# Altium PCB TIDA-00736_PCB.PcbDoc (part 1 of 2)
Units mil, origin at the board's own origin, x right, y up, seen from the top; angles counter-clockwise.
Board outline 3346.46 x 1968.5 mil, 2 copper layers (Top Layer, Bottom Layer), stack 62 mil thick; 81 components, 63 nets, 308 pads, 545 vias.
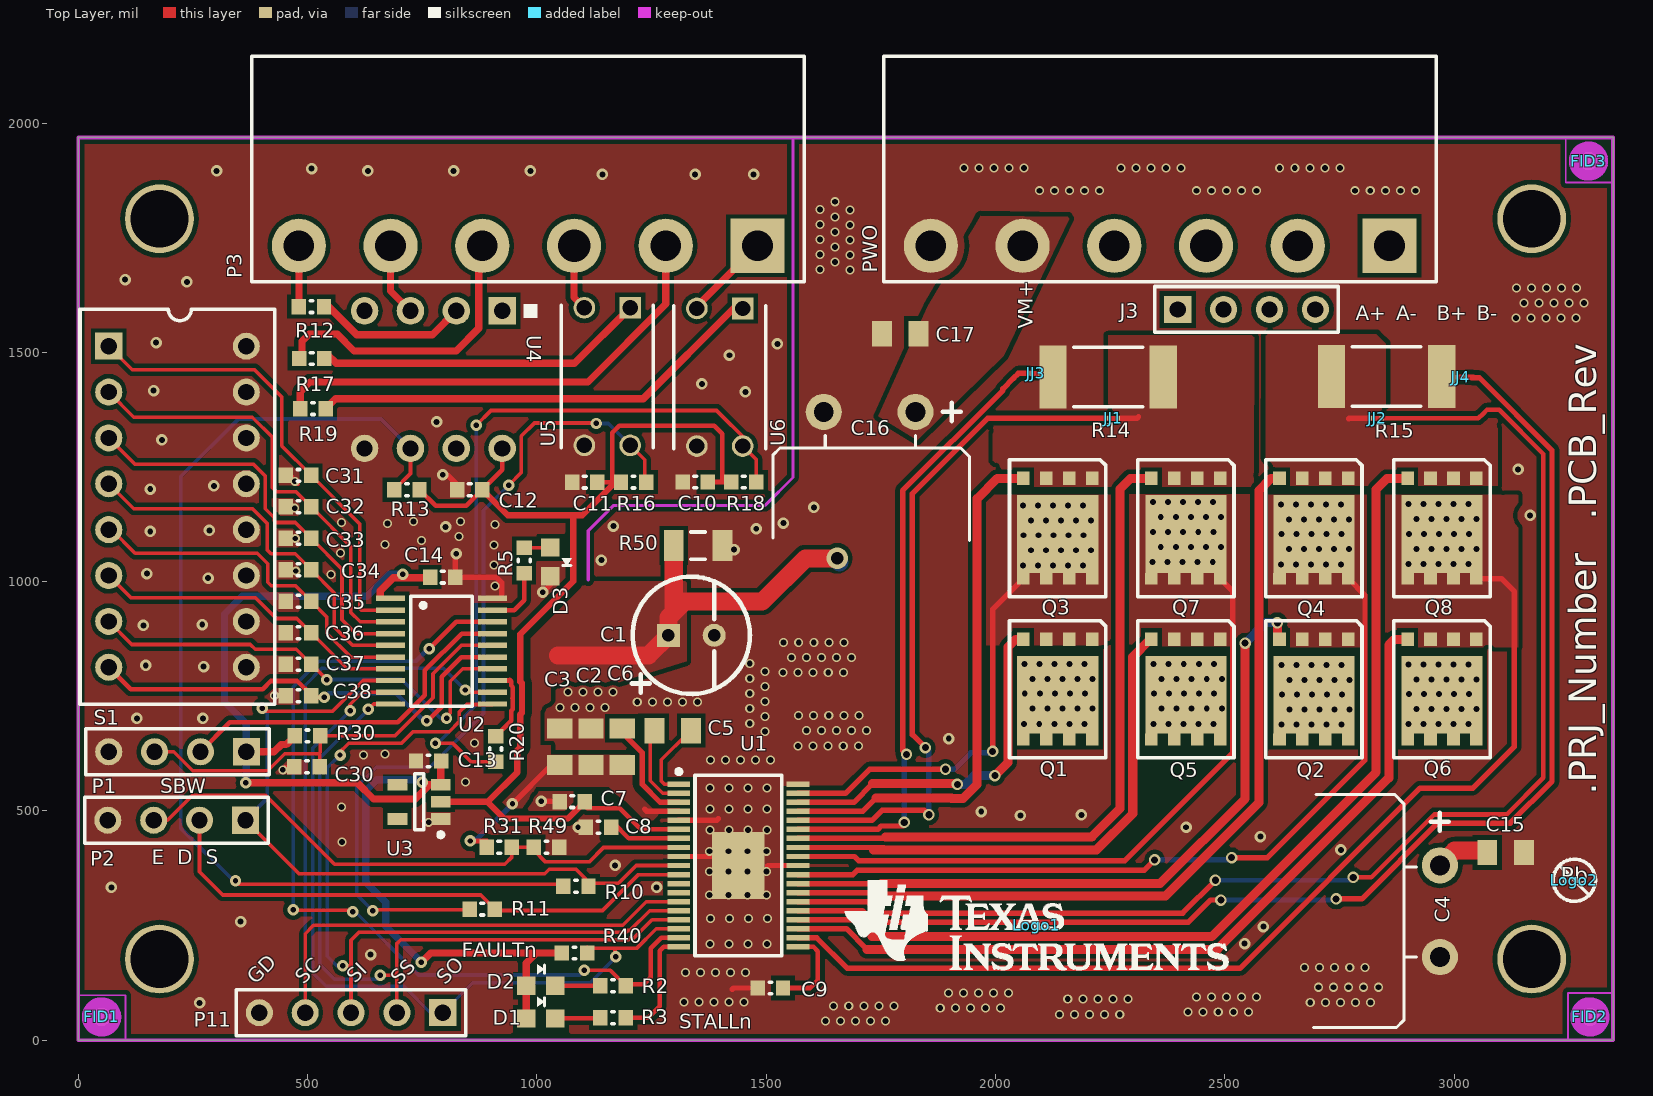
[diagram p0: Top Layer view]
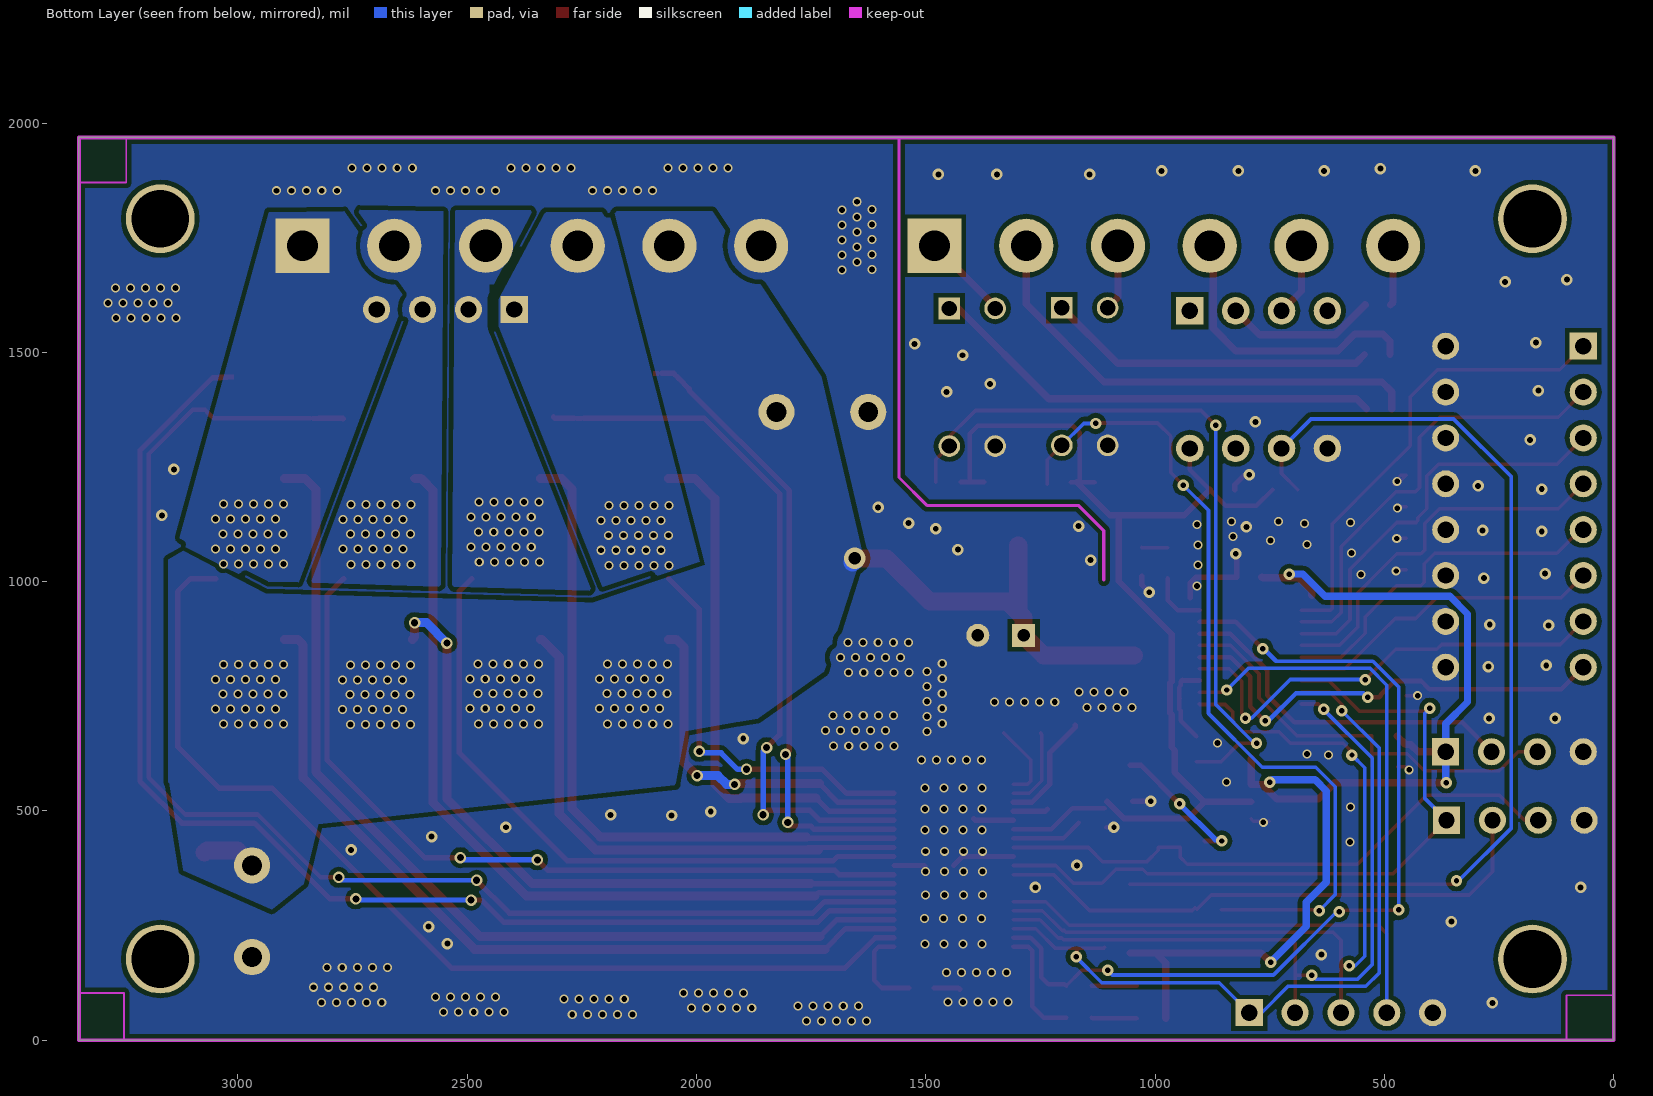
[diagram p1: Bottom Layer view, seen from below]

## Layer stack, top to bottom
Top Solder: solder mask 0.4, Solder Resist, Dk 3.5
Top Layer: signal copper 1.4
Dielectric1: core 59.2, FR-4, Dk 4.8
Bottom Layer: signal copper 1.4
Bottom Solder: solder mask 0.4, Solder Resist, Dk 3.5

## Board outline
0,0 3346.46,0 3346.46,1968.5 0,1968.5

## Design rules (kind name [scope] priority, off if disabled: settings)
AcuteAngle [All] p1: minimum=4.50000000000000E+0001 checktracksonly=FALSE
AssemblyTestPointUsage [All] p1: valid=2
Clearance Clearance_Keepouts [((IsTrack Or IsArc) And Not InPoly) And IsFree and IsKeepOut vs ((IsTrack Or IsArc) And Not InPoly) And IsFree and IsKeepOut] p1: gap=0
Clearance Clearance_BoardEdge_MountingHoles [OnCopper and InComponentClass('Mounting Holes') vs IsKeepOut] p2: gap=8
Clearance Clearance_BoardEdge_Poly [OnCopper and InPoly vs IsKeepOut] p3: gap=10
Clearance Clearance_BoardEdge [OnCopper and Not InComponentClass('Logo') and not InComponentClass('FiducialMark') and not InRegion(1000,500,4000,800) and Not IsKeepout vs IsKeepOut] p4: gap=10
Clearance Clearance_Poly [InPolygon] p5: gap=10
Clearance [All] p6: gap=7.87
ComponentClearance ComponentClearance_MountingHoles_FiducialMarks [InComponentClass('Mounting Holes') vs InComponentClass('FiducialMark')] p1: gap=50 collisioncheckmode=3 verticalgap=10 showdistances=FALSE
ComponentClearance ComponentClearance_Shunt [InComponentClass('Header') vs InComponentClass('Shunt')] p2: gap=0 collisioncheckmode=3 verticalgap=0 showdistances=FALSE
ComponentClearance ComponentClearance_Logo [InComponentClass('Logo')] p3: gap=50 collisioncheckmode=3 verticalgap=10 showdistances=FALSE
ComponentClearance ComponentClearance_ScrewToNut [(HasFootprint('NY PMS 440 0025 PH')) vs (HasFootprint('Keystone_1902C'))] p4: gap=5 collisioncheckmode=3 verticalgap=10 showdistances=FALSE
ComponentClearance ComponentClearance_MountingHoles [InComponentClass('Mounting Holes')] p5: gap=250 collisioncheckmode=3 verticalgap=100000 showdistances=FALSE
ComponentClearance ComponentClearance_SmallPassives [HasFootprint('0201*') or HasFootprint('0402*') or HasFootprint('0508') or HasFootprint('0603*') or HasFootprint('0612') or HasFootprint('0805*') or HasFootprint('0815*') or HasFootprint('0830*') or HasFootprint('1206*') or HasFootprint('1210*') or HasFootprint('1808*') or HasFootprint('1812*') or HasFootprint('1825*') or HasFootprint('2010*') or HasFootprint('2220*') or HasFootprint('2225*') or HasFootprint('2512*') or HasFootprint('2728*') or HasFootprint('3518*') vs HasFootprint('0201*') or HasFootprint('0402*') or HasFootprint('0508') or HasFootprint('0603*') or HasFootprint('0612') or HasFootprint('0805*') or HasFootprint('0815*') or HasFootprint('0830*') or HasFootprint('1206*') or HasFootprint('1210*') or HasFootprint('1808*') or HasFootprint('1812*') or HasFootprint('1825*') or HasFootprint('2010*') or HasFootprint('2220*') or HasFootprint('2225*') or HasFootprint('2512*') or HasFootprint('2728*') or HasFootprint('3518*')] p6: gap=10 collisioncheckmode=3 verticalgap=10 showdistances=FALSE
ComponentClearance ComponentClearance_THtoSMT [IsThruComponent vs IsSMTComponent] p7: gap=10 collisioncheckmode=3 verticalgap=1 showdistances=FALSE
ComponentClearance ComponentClearance_THtoTH [IsThruComponent vs IsThruComponent] p8: gap=1 collisioncheckmode=3 verticalgap=0 showdistances=FALSE
ComponentClearance [All] p9: gap=8 collisioncheckmode=3 verticalgap=10 showdistances=FALSE
DiffPairsRouting [All] p1: maxlimit=100 minlimit=10 mostfreqgap=10 toplayer_minwidth=15 toplayer_maxwidth=15 toplayer_prefwidth=15 bottomlayer_minwidth=15 bottomlayer_maxwidth=15 bottomlayer_prefwidth=15 maxuncoupledlength=1000
FabricationTestPointUsage TestPointUsage [All] p1: valid=2 allowmultiple=FALSE
FabricationTestpoint Testpoint [All] p1: side=3 testpointundercomponent=TRUE minsize=40 maxsize=100 preferedsize=60 minholesize=0 maxholesize=40 preferedholesize=32 testpointgrid=1 allowsidetop=TRUE allowsidebottom=TRUE usegrid=TRUE gridtolerance=0.01
FanoutControl Fanout_LCC [IsLCC] p1: bgadir=Out bgaviamode=Centered fanoutstyle=Auto fanoutdirection=Alternating viagrid=1 // Fanout_LCC (Default Rule)
FanoutControl Fanout_BGA [IsBGA] p2: bgadir=Out bgaviamode=Centered fanoutstyle=Auto fanoutdirection=Alternating viagrid=1 // Fanout_BGA (Default Rule)
FanoutControl Fanout_Default [All] p4: bgadir=Out bgaviamode=Centered fanoutstyle=Auto fanoutdirection=Alternating viagrid=1 // Fanout_Default (Default Rule)
FanoutControl Fanout_Small [(CompPinCount < 5)] p5: bgadir=Out bgaviamode=Centered fanoutstyle=Auto fanoutdirection=OutThenIn viagrid=1 // Fanout_Small (Default Rule)
HoleSize [All] p1: absolutevalues=TRUE maxlimit=251 minlimit=8 maxpercent=80.000 minpercent=20.000
MinimumAnnularRing MinimumAnnularRing_ThermalPadVias [IsVia and InAnyComponent] p1: minimumring=5.91
MinimumAnnularRing [All] p2: minimumring=9
MinimumSolderMaskSliver MinimumSolderMaskSliver_Logo [InComponentClass('Logo') vs InComponentClass('Logo')] p1: minsoldermaskwidth=0.7
MinimumSolderMaskSliver [All] p2: minsoldermaskwidth=3.94
PlaneClearance [All] p1: clearance=15
PlaneConnect [All] p1: planeconnectstyle=Direct reliefexpansion=10 reliefentries=4 reliefconductorwidth=10 reliefairgap=10
PolygonConnect [All] p1: connectstyle=Direct reliefconductorwidth=10 reliefentries=4 polygonreliefangle="90 Angle" airgapwidth=10
RoutingVias ThermalPadVias [IsVia and InAnyComponent] p1: holewidth=7.87 width=19.68 viastyle="Through Hole" minholewidth=7.87 minwidth=19.68 maxholewidth=12.99 maxwidth=23.62
RoutingVias [All] p2: holewidth=16 width=34 viastyle="Through Hole" minholewidth=7.87 minwidth=25 maxholewidth=40 maxwidth=65
SilkToBoardRegionClearance [Not ((IsComment or IsDesignator) And (Hide <> 'False')) and not InRegion(1000,500,4000,800)] p1:
SilkToSilkClearance SilkToSilkClearance_Pb-FreeLogo [(HasFootprint('Pb-Free_Overlay_Medium') OR HasFootprint('Pb-Free_Overlay_Small')) vs (HasFootprint('Pb-Free_Overlay_Medium') OR HasFootprint('Pb-Free_Overlay_Small'))] p1: silktosilkclearance=0
SilkToSilkClearance [All] p2: silktosilkclearance=4
SilkToSolderMaskClearance SilkToComonentPadClearance [IsPad and InAnycomponent] p1: minsilkscreentomaskgap=5 clearancetoexposedcopper=TRUE
SilkToSolderMaskClearance "Silk to Solder Mask Opening" [All] p2: minsilkscreentomaskgap=4 clearancetoexposedcopper=FALSE
SolderMaskExpansion [All] p1: expansion=1.97
UnpouredPolygon [All] p1: allowunpoured=FALSE
Width [All] p1: maxlimit=100 minlimit=6 preferedwidth=10 checkconnectedcopper=TRUE
13 further rules are at their usual default settings.

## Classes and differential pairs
component class TIDA-00736_SCH: C1 C2 C3 C4 C5 C6 C7 C8 C9 C10 C11 C12 C13 C14 C15 C16 C17 C30 C31 C32 C33 C34 C35 C36 C37 C38 D1 D2 D3 J3 JJ1 JJ2 JJ3 JJ4 P1 P2 P3 P11 PWO Q1 Q2 Q3 Q4 Q5 Q6 Q7 Q8 R2 R3 R5 R10 R11 R12 R13 R14 R15 R16 R17 R18 R19 R20 R30 R31 R40 R49 R50 S1 U1 U2 U3 U4 U5 U6
component class Header: J3 P1 P2 P11
component class AssemblyNote: ZZ2 ZZ3 ZZ4
component class FiducialMark: FID1 FID2 FID3
component class TIDA-00736_Hardware: FID1 FID2 FID3 Logo1 Logo2 ZZ2 ZZ3 ZZ4
component class Logo: Logo1

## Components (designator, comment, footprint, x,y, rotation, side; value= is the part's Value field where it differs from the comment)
C1 "UBT2A220MPD1TD" "RB .1/.250 - SML" 1386.61,883.07 r0 top
C2 "C2012X7R2A104K" C0805M 1118,640 r90 top
C3 "08051C103JAT2A" C0805M 1050,640 r90 top
C4 "EKYB630ELL331MJ25S" CAP13-5 2968.9,181.5 r270 top locked
C5 "C2012X7R2A104K" C0805M 1296.46,675.2 r180 top
C6 "08055C105KAT2A" C0805M 1186,640 r270 top
C7 "C0603X104K4RACTU" 0603l 1077.17,520.47 r180 top
C8 "C0603C105K4PACTU" 0603l 1134.25,464.57 r180 top
C9 "885012206034" 0603l 1509.06,114.17 r180 top
C10 "CGA3E2X8R1E104K080AA" 0603l 1345.28,1217.32 r0 top
C11 "CGA3E2X8R1E104K080AA" 0603l 1104.33,1216.93 r0 top
C12 "CGA3E2X8R1E104K080AA" 0603l 853.54,1200.39 r0 top
C13 "C0603C105K4PACTU" 0603l 764,609 r0 top
C14 "C0603C105K4PACTU" 0603l 794.88,1009.84 r180 top
C15 "C2012X7R2A104K" C0805M 3112.21,409.45 r180 top
C16 "860040875005" CAP10-5 1825.59,1370.08 r0 top locked
C17 "C2012X7R2A104K" C0805m 1792.35,1540.61 r0 top
C30 "885012206034" 0603l 498.82,596.46 r0 top
C31 "CGA3E2X8R1E104K080AA" 0603l 480.32,1231.89 r0 top
C32 "CGA3E2X8R1E104K080AA" 0603l 480.32,1163.22 r0 top
C33 "CGA3E2X8R1E104K080AA" 0603l 480.32,1094.54 r0 top
C34 "CGA3E2X8R1E104K080AA" 0603l 480.32,1025.87 r0 top
C35 "CGA3E2X8R1E104K080AA" 0603l 480.32,957.2 r0 top
C36 "CGA3E2X8R1E104K080AA" 0603l 480.32,888.53 r0 top
C37 "CGA3E2X8R1E104K080AA" 0603l 480.32,819.85 r0 top
C38 "CGA3E2X8R1E104K080AA" 0603l 480.32,751.18 r0 top
D1 "LTST-C191KRKT" LED603RED 1007.87,47.64 r180 top
D2 "LTST-C191KRKT" LED603RED 1007.87,118.9 r180 top
D3 "LTST-C191TGKT" LED603RED 1029.13,1043.7 r90 top
FID1 "Fiducial" Fiducial10-20 51,51 r0 top
FID2 "Fiducial" Fiducial10-20 3296,51 r0 top
FID3 "Fiducial" Fiducial10-20 3293,1917 r0 top
J3 "800-10-004-10-001000" HDR1X4 2397.35,1593.61 r0 top
JJ1 "Net-Tie" NETCC 2256.3,1355.91 r0 top net-tie
JJ2 "Net-Tie" NETCC 2832.28,1355.91 r180 top net-tie
JJ3 "Net-Tie" NETCC 2088,1454 r0 top net-tie
JJ4 "Net-Tie" netcc 3014.57,1446.06 r180 top net-tie
Logo1 "Texas Instruments" TI_Stacked_Overlay_Small 2090,251 r0 top
Logo2 "Pb-Free Symbol" Pb-Free_Overlay_Small 3262,349 r0 top
P1 "800-10-004-10-001000" HDR1X4 366.54,629.13 r180 top
P2 "800-10-004-10-001000" HDR1X4 364.57,479.92 r180 top
P3 "Header 6" cn508-6 1181.1,1732.28 r180 top locked
P11 "800-10-005-10-001000" HDR1X5 794.88,60.24 r180 top
PWO "Header 6" cn508-6 2559.06,1732.28 r180 top locked
Q1 "CSD18531Q5A" PQFN8 2210.63,874.41 r90 top
Q2 "CSD18531Q5A" PQFN8 2769.16,874.41 r90 top
Q3 "CSD18531Q5A" PQFN8 2210.63,1225.08 r90 top locked
Q4 "CSD18531Q5A" PQFN8 2769.16,1225.08 r90 top
Q5 "CSD18531Q5A" PQFN8 2489.9,874.41 r90 top
Q6 "CSD18531Q5A" PQFN8 3048.43,874.41 r90 top
Q7 "CSD18531Q5A" PQFN8 2489.9,1225.08 r90 top
Q8 "CSD18531Q5A" PQFN8 3048.43,1225.08 r90 top
R2 "RC0603JR-0710KL" 0603l 1166.14,119.06 r180 top
R3 "RC0603JR-0710KL" 0603l 1166.14,49.21 r180 top
R5 "RC0603JR-0710KL" 0603l 972.44,1046.06 r270 top
R10 "CRCW0603470RJNEA" 0603l 1085,336 r180 top
R11 "CRCW0603470RJNEA" 0603l 881,286 r180 top
R12 "CRCW0603220RJNEA" 0603l 508.35,1599.61 r180 top
R13 "CRCW06033K30JNEA" 0603l 716.54,1200.39 r180 top
R14 "CRA2512-FZ-R040ELF" 2512M 2245.67,1446.46 r0 top
R15 "CRA2512-FZ-R040ELF" 2512M 2852.76,1447.24 r180 top
R16 "CR0603-JW-472GLF" 0603l 1211.02,1216.93 r0 top
R17 "CRCW0603220RJNEA" 0603l 509.35,1486.61 r180 top
R18 "CR0603-JW-472GLF" 0603l 1451.18,1217.32 r0 top
R19 "CRCW0603220RJNEA" 0603l 511.81,1377.17 r180 top
R20 "CRCW0603470RJNEA" 0603l 910,635 r270 top
R30 "CRCW060347K0JNEA" 0603l 500,663.78 r0 top
R31 "CRCW0603100KJNEA" 0603l 918,421 r0 top
R40 "CRCW060347K0JNEA" 0603l 1082.28,190.55 r0 top
R49 "RC0603JR-0710KL" 0603l 1021,421 r0 top
R50 "CRCW120610K0JNEA" C1206 1351.58,1078.74 r0 top
S1 "76SB08ST" DIP-16-KEY 66.54,1513.39 r270 top
U1 "DRV8711" "DCP38 SMT" 1309.45,558.27 r270 top
U2 "MSP430G2202IPW20" DGV0020A_L 792.13,848.43 r0 top
U3 "TLV70433DBVR" MF05A_N 743.31,520.08 r180 top
U4 "6N137S(TA)" DIP8 774.41,1440.55 r180 top
U5 "PC817X4NSZ0F" DIP762W60P254L460H350Q4B 1153.54,1447.24 r270 top
U6 "PC817X4NSZ0F" DIP762W60P254L460H350Q4B 1398.82,1445.67 r270 top
ZZ2 "These assemblies are ESD sensitive, ESD precautions shall be observed." AssemblyNote -96.65,3428.72 r0 top
ZZ3 "These assemblies must be clean and free from flux and all contaminants. Use of no clean flux is not acceptable." AssemblyNote -96.65,3340.16 r0 top
ZZ4 "These assemblies must comply with workmanship standards IPC-A-610 Class 2, unless otherwise specified." AssemblyNote -96.65,3251.61 r0 top

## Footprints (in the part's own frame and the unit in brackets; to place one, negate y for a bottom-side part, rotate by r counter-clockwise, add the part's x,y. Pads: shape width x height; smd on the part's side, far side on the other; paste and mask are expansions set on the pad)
0603l [mm] "0603 from SM-752 data"
  rect 0.8x0.85 smd: 1(-0.7,0) 2(0.7,0)
  silkscreen extent -0.07,-0.33 0.07,0.33, body extent -0.87,-0.47 0.87,0.47, height 0.85
2512M [mm] "Chip Resistor, Body 6.3x3.2mm, IPC Low Density"
  rect 1.5x3.5 smd: 1(-3.05,0) 2(3.05,0)
  silkscreen extent -1.9,-1.65 1.9,1.65, body extent -3.22,-1.67 3.22,1.67, height 0.71
AssemblyNote [mil] "Assembly Note"
C0805M [mm]
  rect 1.1x1.4 smd: 1(-1.016,0) 2(1.016,0)
  body extent -1.1,-0.72 1.1,0.72, height 1.4
C0805m [mm]
  rect 1.1x1.4 smd: 1(-1.016,0) 2(1.016,0)
  body extent -1.1,-0.72 1.1,0.72, height 1.4
C1206 [mm] "Chip Capacitor, Body 3.2x1.6mm, IPC High Density"
  rect 1.1x1.7 smd: 1(-1.35,0) 2(1.35,0)
  silkscreen extent -0.4,-0.75 0.4,0.75, body extent -1.7,-0.9 1.7,0.9, height 1.3
CAP10-5 [mm] "Small Form Factor"
  round 2 hole 1.1: 1(0,0) 2(-5.08,0)
  silkscreen extent -7.9,-7.11 3,0.5
CAP13-5 [mm] "Small Form Factor"
  round 2 hole 1.1: 1(-5.08,0) 2(0,0)
  silkscreen extent -9,-6.98 3.9,0.5
cn508-6 [mm] "Connector; Header; 4 Position"
  rect 3x3 hole 1.7: 1(-7.62,0)
  round 3 hole 1.7: 2(-2.54,0) 4(7.62,0) 5(12.7,0) 6(17.78,0)
  round 3 hole 1.8: 3(2.54,0)
  silkscreen extent -10.2,-10.5 20.4,2
"DCP38 SMT" [mm] "DCP 38 Pin  Solder"
  rect 3.7x2.9 smd: 0(4.5,3.3)
  rect 0.3x1.25 smd: 1(0,0) 2(0.5,0) 3(1,0) 4(1.5,0) 5(2,0) 6(2.5,0) 7(3,0) 8(3.5,0) 9(4,0) 10(4.5,0) 11(5,0) 12(5.5,0) 13(6,0) 14(6.5,0) 15(7,0) 16(7.5,0) 17(8,0) 18(8.5,0) 19(9,0) 20(9,6.6) 21(8.5,6.6) 22(8,6.6) 23(7.5,6.6) 24(7,6.6) 25(6.5,6.6) 26(6,6.6) 27(5.5,6.6) 28(5,6.6) 29(4.5,6.6) 30(4,6.6) 31(3.5,6.6) 32(3,6.6) 33(2.5,6.6) 34(2,6.6) 35(1.5,6.6) 36(1,6.6) 37(0.5,6.6) 38(0,6.6)
  silkscreen extent -0.82,-0.12 9.5,5.7
DGV0020A_L [mm] "TSSOP, 20-Leads, Body 5x4.4mm, Pitch 0.4mm, IPC High Density"
  rect 1.6x0.3 smd: 1(-2.825,2.925) 2(-2.825,2.275) 3(-2.825,1.625) 4(-2.825,0.975) 5(-2.825,0.325) 6(-2.825,-0.325) 7(-2.825,-0.975) 8(-2.825,-1.625) 9(-2.825,-2.275) 10(-2.825,-2.925) 11(2.825,-2.925) 12(2.825,-2.275) 13(2.825,-1.625) 14(2.825,-0.975) 15(2.825,-0.325) 16(2.825,0.325) 17(2.825,0.975) 18(2.825,1.625) 19(2.825,2.275) 20(2.825,2.925)
  silkscreen extent -1.7,-3.05 1.7,3.05
DIP8 [mil]
  rect 60x60 hole 35.43: 1(-150,-150)
  round 60 hole 35.43: 2(-50,-150) 3(50,-150) 4(150,-150) 5(150,150) 6(50,150) 7(-50,150) 8(-150,150)
  silkscreen extent -227,-165 -197,-135
DIP762W60P254L460H350Q4B [mm] "LITE-ON"
  rect 1.2x1.2 hole 0.85: 1(-3.81,1.27)
  round 1.2 hole 0.85: 2(-3.81,-1.27) 3(3.81,-1.27) 4(3.81,1.27)
  silkscreen extent -3.96,-2.55 3.96,2.55, body extent -3.96,-2.55 3.96,2.55, height 4.5
DIP-16-KEY [mm] "DIP; 16 Leads; Row Spacing 7.62 mm; Pitch 2.54 mm"
  rect 1.5x1.5 hole 0.9: 1(0,0)
  round 1.5 hole 0.9: 2(2.54,0) 3(5.08,0) 4(7.62,0) 5(10.16,0) 6(12.7,0) 7(15.24,0) 8(17.78,0) 9(17.78,7.62) 10(15.24,7.62) 11(12.7,7.62) 12(10.16,7.62) 13(7.62,7.62) 14(5.08,7.62) 15(2.54,7.62) 16(0,7.62)
  silkscreen extent -2.05,-1.59 19.83,9.2
Fiducial10-20 [mm]
  round 1 smd mask+0.5: 1(0,0)
  Top Layer keep-out circle w1.178: c0,0 r0.5
HDR1X4 [mm] "Connector; Header; 4 Position"
  rect 1.5x1.5 hole 0.9: 1(0,0)
  round 1.5 hole 0.9: 2(2.54,0) 3(5.08,0) 4(7.62,0)
  silkscreen extent -1.27,-1.27 8.89,1.27
HDR1X5 [mm] "Connector; Header; 5 Position"
  rect 1.5x1.5 hole 0.9: 1(0,0)
  round 1.5 hole 0.9: 2(2.54,0) 3(5.08,0) 4(7.62,0) 5(10.16,0)
  silkscreen extent -1.27,-1.27 11.43,1.27
LED603RED [mil]
  rect 40x40 smd: 1(30.8,-0.1) 2(-32.2,-0.1)
  silkscreen extent -10,-47 7,-25, body extent -26,-29 26,29, height 43
MF05A_N [mm] "SOT23, 5-Leads, Body 2.9x1.6mm, Pitch 0.95mm, Lead Span 2.8mm, IPC Medium Density"
  rect 1.1x0.65 smd: 1(-1.2,0.95) 2(-1.2,0) 3(-1.2,-0.95) 4(1.2,-0.95) 5(1.2,0.95)
  silkscreen extent -1.33,-1.55 0.25,1.95, body extent -0.9,-1.55 0.9,1.55, height 1.19
NETCC [mil] "10mil net tie, no solder mask opening, no solder paste"
  rect 10x10 smd paste-5 mask-5: 1(-10,0) 2(10,0)
  Top Layer region: -6,5 6,5 6,-5 -6,-5
netcc [mil] "10mil net tie, no solder mask opening, no solder paste"
  rect 10x10 smd paste-5 mask-5: 1(-10,0) 2(10,0)
  Top Layer region: -6,5 6,5 6,-5 -6,-5
Pb-Free_Overlay_Small [mil]
  silkscreen extent -46,-46 46,46
PQFN8 [mm]
  rect 0.75x0.7 smd: 1(0,0) 2(0,1.27) 3(0,2.54) 4(0,3.81)
  rect 0.65x0.7 smd: 5(-5.55,0) 5(-5.55,1.27) 5(-5.55,2.54) 5(-5.55,3.81)
  rect 4.3x4.5 smd: 5(-3.075,1.9)
  silkscreen extent -6.55,-0.76 1.03,4.57
"RB .1/.250 - SML" [mil] "Small Form Factor"
  rect 50x50 hole 28: 1(-100,0)
  round 50 hole 28: 2(0,0)
  silkscreen extent -180,-128 78,128
TI_Stacked_Overlay_Small [mil]
  silkscreen extent -418,-98 418,98

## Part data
C1: "CAP, AL, 22 μF, 100 V, +/- 20%, 0.8 ohm, TH"
C2 C5 C15 C17: "CAP, CERM, 0.1 μF, 100 V, +/- 10%, X7R, 0805"
C3: "CAP, CERM, 0.01 μF, 100 V, +/- 5%, X7R, 0805"
C4: "CAP, AL, 330 μF, 63 V, +/- 20%, 0.045 ohm, TH"
C6: "CAP, CERM, 1 μF, 50 V, +/- 10%, X7R, 0805"
C7: "CAP, CERM, 0.1 μF, 16 V, +/- 10%, X7R, 0603"
C8 C13 C14: "CAP, CERM, 1 μF, 16 V, +/- 10%, X5R, 0603"
C9 C30: "CAP, CERM, 1000 pF, 16 V, +/- 10%, X7R, 0603"
C10 C11 C12 C31 C32 C33 C34 C35 C36 C37 C38: "CAP, CERM, 0.1 μF, 25 V, +/- 10%, X8R, AEC-Q200 Grade 0, 0603"
C16: "CAP, AL, 100 μF, 100 V, +/- 20%, 0.2 ohm, TH"
D1 D2: "LED, Red, SMD"
D3: "LED, Green, SMD"
FID1 FID2 FID3: "Fiducial mark.  There is nothing to buy or mount."
J3 P1 P2: "Header, 100mil, 4x1, TH"
JJ1 JJ2 JJ3 JJ4: "Single point connection between nets."
Logo1: library part TI_Logo, "Texas Instrument Corporate Signature"
Logo2: library part Pb-Free
P3 PWO: "Header, 6-Pin"
P11: "Header, 100mil, 5x1, TH"
Q1 Q2 Q3 Q4 Q5 Q6 Q7 Q8: "MOSFET, N-CH, 60 V, 19 A, SON 5x6mm"
R2 R3 R5 R49: "RES, 10 k, 5%, 0.1 W, 0603"
R10 R11 R20: "RES, 470, 5%, 0.1 W, 0603"
R12 R17 R19: "RES, 220, 5%, 0.1 W, 0603"
R13: "RES, 3.3 k, 5%, 0.1 W, 0603"
R14 R15: "RES, 0.04, 1%, 3 W, 2512"
R16 R18: "RES, 4.7 k, 5%, 0.1 W, 0603"
R30 R40: "RES, 47 k, 5%, 0.1 W, 0603"
R31: "RES, 100 k, 5%, 0.1 W, 0603"
R50: "RES, 10 k, 5%, 0.25 W, 1206"
S1: "Switch, SPST 8Pos, Rocker, TH"
U1: "Pre Driver Stepper Motor Controller"
U2: "16 MHz Mixed Signal Microcontroller with 2 KB Flash, 256 B SRAM and 16 GPIOs, 20-pin SOP (PW), Green (RoHS & no Sb/Br)"
U3: "Single Output LDO, 150 mA, Fixed 3.3 V Output, 2.5 to 24 V Input, with Ultra-Low IQ, 5-pin SOT-23 (DBV), -40 to 125 degC, Green (RoHS & no Sb/Br)"
U4: "HIGH SPEED 10MBit/s LOGIC GATE PHOTOCOUPLER, SMT"
U5 U6: "Optocoupler, 5 kV, 300-600% CTR, TH-4"
ZZ2 ZZ3 ZZ4: library part AssemblyNote

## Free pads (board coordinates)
  round 150 hole 125.98: 3(177.17,177.17) 3(177.17,1791.34) 3(3169.29,177.17) 3(3169.29,1791.34)

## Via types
v1: diameter 19.68, hole 13, Top Layer to Bottom Layer, 434 vias
v2: diameter 25, hole 13, Top Layer to Bottom Layer, 54 vias
v3: diameter 25, hole 11.81, Top Layer to Bottom Layer, 17 vias
v4: diameter 25, hole 12, Top Layer to Bottom Layer, 16 vias
v5: diameter 25, hole 15.75, Top Layer to Bottom Layer, 16 vias
v6: diameter 19.68, hole 11.81, Top Layer to Bottom Layer, 7 vias
v7: diameter 47.24, hole 27.56, Top Layer to Bottom Layer, 1 vias

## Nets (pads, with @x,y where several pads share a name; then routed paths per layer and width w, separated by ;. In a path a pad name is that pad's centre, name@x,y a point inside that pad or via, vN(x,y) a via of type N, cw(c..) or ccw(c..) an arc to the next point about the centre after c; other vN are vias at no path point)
A1HS: Q1.4 U1.36 | length 787.8
  Top Layer w11.81: U1.36@1569.29,518.9 1690.95,518.9 1731.89,559.84
  Top Layer w19.68: 1731.89,559.84 1914.96,559.84 v5(1916.93,557.87) ; v5(1998.82,577.17) 2027.56,605.91 2027.56,857.87 2044.1,874.41 Q1.4@2060.63,874.41
  Bottom Layer w19.68: v5(1916.93,557.87) 1934.25,557.87 1953.54,577.17 v5(1998.82,577.17)
A1LS: Q3.4 U1.35 | length 1157.5
  Top Layer w11.81: U1.35@1569.29,499.21 1710.24,499.21 1739.37,528.35
  Top Layer w19.68: 1739.37,528.35 1903.72,528.35 1904.41,527.66 1929.44,527.66 1959.74,557.96 1959.74,1181 2003.82,1225.08 Q3.4@2060.63,1225.08
A2HS: Q5.4 U1.31 | length 1183.5
  Top Layer w11.81: U1.31@1569.29,420.47 1756.3,420.47
  Top Layer w19.68: 1733.86,414.96 2220.08,414.96 2299.21,494.09 2299.21,835.75 2337.87,874.41 Q5.4@2339.9,874.41
A2LS: Q7.4 U1.32 | length 1513.1
  Top Layer w11.81: U1.32@1569.29,440.16 1771.26,440.16
  Top Layer w19.68: 1760.63,443.7 2209.85,443.7 2271.65,505.51 2271.65,1202.36 2294.37,1225.08 Q7.4@2339.9,1225.08
AISENN: JJ3.1 U1.33 | length 1357.5
  Top Layer w11.81: U1.33@1569.29,459.84 1743.37,459.84 1750.85,467.32 1798.82,467.32 1801.97,470.47 1800.79,471.65 v5(1800.79,475.2) ; v5(1805.91,623.23) 1797.64,631.5 1797.64,1198.43 2016.14,1416.93 2016.14,1420.47 2039.37,1443.7 2050,1454.33 JJ3.1@2076,1454.33
  Bottom Layer w11.81: v5(1800.79,475.2) 1800.79,618.11 v5(1805.91,623.23)
AISENP: JJ1.1 U1.34 | length 1524.6
  Top Layer w11.81: U1.34@1569.29,479.53 1730.71,479.53 1752.66,501.48 1844.98,501.48 v5(1854.72,491.73) ; v5(1847.24,638.19) 1818.9,666.54 1818.9,1191.85 1982.96,1355.91 2045.28,1355.91 ; JJ1.1@2246.3,1355.91 2061.02,1355.91 ; 2045.28,1355.91 2061.02,1355.91 ; 2045.28,1355.91 2061.02,1355.91
  Bottom Layer w11.81: v5(1847.24,638.19) 1854.72,630.71 v5(1854.72,491.73)
AOUT1: J3.1 PWO.4 Q1.1 Q1.2 Q1.3 Q3.5 U1.37 | length 866.6
  Top Layer w11.81: U1.37@1569.29,538.58 1672.84,538.58 1725.2,590.95 v5(1890.95,590.95) ; v5(1993.7,629.92) 1993.7,939.65 Q3.5@2060.63,1006.58
  Bottom Layer w11.81: v5(1890.95,590.95) 1910.63,590.95 1946.46,626.77 1990.55,626.77 v5(1993.7,629.92)
  other v1: 2059.45,1035.43 2092.23,1035.43 2125,1035.43 2157.78,1035.43 2190.55,1035.43 2077.17,1068.5 2109.94,1068.5 2142.72,1068.5 2175.49,1068.5 2208.27,1068.5 2060.63,1101.18 2093.41,1101.18 2126.18,1101.18 2158.96,1101.18 2191.73,1101.18 2077.17,1133.07 2109.94,1133.07 2142.72,1133.07 2175.49,1133.07 2208.27,1133.07 2059.84,1165.75 2092.62,1165.75 2125.39,1165.75 2158.17,1165.75 2190.95,1165.75
AOUT2: J3.2 PWO.3 Q5.1 Q5.2 Q5.3 Q7.5 U1.30 | length 1440.5
  Top Layer w11.81: U1.30@1569.29,400.79 1692.52,400.79 1701.97,391.34 2281.5,391.34 2517.45,627.3 2517.45,979.02 Q7.5@2489.9,1006.58
  other v1: 2342.52,1042.91 2375.3,1042.91 2408.07,1042.91 2440.85,1042.91 2473.62,1042.91 2360.24,1075.98 2393.01,1075.98 2425.79,1075.98 2458.56,1075.98 2491.34,1075.98 2343.7,1108.66 2376.48,1108.66 2409.25,1108.66 2442.03,1108.66 2474.8,1108.66 2360.24,1140.55 2393.01,1140.55 2425.79,1140.55 2458.56,1140.55 2491.34,1140.55 2342.91,1173.23 2375.69,1173.23 2408.47,1173.23 2441.24,1173.23 2474.02,1173.23
B1HS: Q2.4 U1.27 | length 1544.2
  Top Layer w11.81: U1.27@1569.29,341.73 1777.95,341.73
  Top Layer w19.68: 1751.18,342.13 2359.06,342.13 2544.1,527.16 v5(2544.1,866.14) ; v5(2614.57,910.63) 2614.57,879 Q2.4@2619.16,874.41
  Bottom Layer w19.68: v5(2544.1,866.14) 2588.58,910.63 v5(2614.57,910.63)
B1LS: Q4.4 U1.26 | length 1881.3
  Top Layer w11.81: U1.26@1569.29,322.05 1733.46,322.05 1741.73,313.78 1794.49,313.78 ; Q4.4@2613.27,1225.08 Q4.4@2619.16,1225.08
  Top Layer w19.68: 1742.13,314.57 2370.47,314.57 2574.31,518.41 2574.31,1198.72 2600.67,1225.08 Q4.4@2613.27,1225.08
B2HS: Q6.4 U1.22 | length 1797.7
  Top Layer w11.81: U1.22@1569.29,243.31 1674.8,243.31 1719.69,198.43
  Top Layer w19.68: 1719.69,198.43 2483.86,198.43 2857.48,572.05 2857.48,862.21 2869.69,874.41 Q6.4@2898.43,874.41
B2LS: Q8.4 U1.23 | length 2119.5
  Top Layer w11.81: U1.23@1569.29,262.99 1694.09,262.99 1731.1,225.98
  Top Layer w19.68: 1731.1,225.98 2471.26,225.98 2829.92,584.65 2829.92,1201.18 2853.82,1225.08 Q8.4@2898.43,1225.08
BEMF: C9.1 U1.20 | length 193.8
  Top Layer w10: C9.1@1536.61,114.17 1596.06,114.17 1612.6,130.71 1612.6,194.49 1603.15,203.94 U1.20@1569.29,203.94
BISENN: JJ4.1 U1.24 | length 2760.5
  Top Layer w11.81: U1.24@1569.29,282.68 1709.84,282.68 1735.04,257.48 2420.47,257.48 2468.9,305.91 v5(2491.34,305.91) ; v5(2742.52,308.27) 2798.61,308.27 2963.96,473.62 3122.23,473.62 3213.27,564.66 3213.27,1286.13 3054.79,1444.61 3038.35,1444.61 ; JJ4.1@3024.57,1446.06 3041.34,1446.06
  Bottom Layer w11.81: v5(2491.34,305.91) 2740.16,305.91 v5(2742.52,308.27)
BISENP: JJ2.1 U1.25 | length 2863.8
  Top Layer w10: v5(2779.92,355.12) 2818.9,355.12 2956.18,492.4 3114.45,492.4 3194.49,572.44 3194.49,1278.35 3098.03,1374.8 3071.65,1374.8 3062.99,1366.14 3052.76,1355.91 JJ2.1@2842.28,1355.91
  Top Layer w11.81: U1.25@1569.29,302.36 1720.87,302.36 1746.06,277.17 2407.87,277.17 v5(2479.53,348.82)
  Bottom Layer w10: v5(2479.53,348.82) 2773.62,348.82 v5(2779.92,355.12)
BOUT1: J3.3 PWO.2 Q2.1 Q2.2 Q2.3 Q4.5 U1.28 | length 1750.2
  Top Layer w11.81: U1.28@1569.29,361.42 1689.26,361.42 1698.31,370.47 2324.02,370.47 v5(2346.85,393.31) ; v5(2514.57,398.43) 2592.91,398.43 2805.51,611.02 2805.51,970.22 Q4.5@2769.16,1006.58
  Bottom Layer w11.81: v5(2346.85,393.31) 2509.45,393.31 v5(2514.57,398.43)
  other v1: 2622.05,1037.8 2654.82,1037.8 2687.6,1037.8 2720.38,1037.8 2753.15,1037.8 2639.77,1070.87 2672.54,1070.87 2705.32,1070.87 2738.09,1070.87 2770.87,1070.87 2623.23,1103.54 2656.01,1103.54 2688.78,1103.54 2721.56,1103.54 2754.33,1103.54 2639.77,1135.43 2672.54,1135.43 2705.32,1135.43 2738.09,1135.43 2770.87,1135.43 2622.44,1168.11 2655.22,1168.11 2687.99,1168.11 2720.77,1168.11 2753.54,1168.11
BOUT2: J3.4 PWO.1 Q6.1 Q6.2 Q6.3 Q8.5 U1.21 | length 2222.4
  Top Layer w11.81: U1.21@1569.29,223.62 1610.02,223.62 1676.95,156.69 2532.68,156.69 2925.98,550 3040.95,550 3131.1,640.16 3131.1,978.35 3102.76,1006.69 3048.54,1006.69 Q8.5@3048.43,1006.58
  other v1: 2900,1038.58 2932.78,1038.58 2965.55,1038.58 2998.33,1038.58 3031.1,1038.58 2917.72,1071.65 2950.49,1071.65 2983.27,1071.65 3016.04,1071.65 3048.82,1071.65 2901.18,1104.33 2933.96,1104.33 2966.73,1104.33 2999.51,1104.33 3032.28,1104.33 2917.72,1136.22 2950.49,1136.22 2983.27,1136.22 3016.04,1136.22 3048.82,1136.22 2900.39,1168.9 2933.17,1168.9 2965.95,1168.9 2998.72,1168.9 3031.5,1168.9
COM1+: P3.6 R12.2 | length 130.6
  Top Layer w15.75: P3.6@481.1,1732.28 481.1,1609.45 R12.2@486.61,1603.94
COM2+: P3.4 R17.2 | length 639.3
  Top Layer w15.75: R17.2@488.19,1495.28 488.19,1524.41 503.54,1539.76 564.96,1539.76 601.58,1503.15 824.02,1503.15 873.23,1552.36 873.23,1724.41 P3.4@881.1,1732.28
COM3+: P3.2 R19.2 | length 1040
  Top Layer w15.75: R19.2@484.25,1377.17 484.25,1414.17 505.51,1435.43 1111.25,1435.43 1281.1,1605.29 P3.2@1281.1,1732.28
CP1: C5.1 U1.1 | length 170.1
  Top Layer w7.87: U1.1@1309.45,558.27 1278.35,558.27 1271.26,565.35 1271.26,611.58 C5.1@1329.76,670.08
CP2: C5.2 U1.2 | length 178.8
  Top Layer w7.87: C5.2@1249.76,670.08 1247.24,667.56 1247.24,565.75 1274.41,538.58 U1.2@1309.45,538.58
DIR: P3.3 U5.2 | length 144.3
  Top Layer w15.75: P3.3@1081.1,1732.28 1081.1,1619.69 U5.2@1103.54,1597.24
DIR_AIN2: P2.2 R11.1 U1.11 | length 1221.8
  Top Layer w7.87: R11.1@913,289.37 919.37,283 1143.24,283 1221.65,361.42 U1.11@1309.45,361.42
  Top Layer w8: P2.2@264.57,479.92 264.57,367.43 315,317 877.56,317 R11.1@908.56,286
DIR_ISO: R11.2 R16.2 U5.4 | length 1848.2
  Top Layer w7.87: v4(642.13,282.68) 644.45,285 R11.2@856,285 ; v4(938.58,1210.24) 966.22,1237.87 966.22,1317.4 994.88,1346.06 1128.35,1346.06 v4(1129.53,1344.88) ; U5.4@1203.54,1297.24 1235.04,1265.75 R16.2@1235.04,1212.99
  Bottom Layer w7.87: v4(642.13,282.68) 607,317.8 607,553 649.67,595.67 766.67,595.67 883.76,712.76 883.76,1155.41 v4(938.58,1210.24) ; v4(1129.53,1344.88) 1155.91,1344.88 U5.4@1203.54,1297.24
EN: R20.1 U2.13 | length 182.1
  Top Layer w10: U2.13@903.35,784.45 941,784.45 941,785.9 944.24,782.66 944.24,773.58 947.72,770.1 947.72,747.62 946.16,746.06 947.72,744.51 947.72,722.03 944.24,718.55 944.24,696.8 R20.1@910,662.56
ENN: P3.1 U6.2 | length 191.4
  Top Layer w15.75: U6.2@1348.82,1595.67 1348.82,1600 P3.1@1481.1,1732.28
ENN_ISO: R18.2 R20.2 U6.4 | length 1602.7
  Top Layer w7.87: v4(867.72,1340.95) 900,1373.23 1391.73,1373.23 U6.4@1459.06,1305.91 ; U6.4@1448.82,1295.67 1478.74,1265.75 R18.2@1478.74,1217.32
  Top Layer w8: v4(779,648) 816,648 856.56,607.44 R20.2@910,607.44
  Bottom Layer w7.87: v4@786.96,651 868.01,732.06 868.01,1344.59 867.72,1344.88 v4(867.72,1340.95)
FAULTN: R2.1 U1.18 U2.18 | length 1977.8
  Top Layer w7.87: v3(468.5,284.65) 469.29,283.86 595.28,283.86 v3(598.82,280.32) ; v3(1103.15,152.36) 1160.39,152.36 R2.1@1193.7,119.06
  Top Layer w10: v3(765.35,853.94) 765.35,853.54 824.21,912.4 U2.18@903.35,912.4 ; R2.1@1193.7,119.06 1196.69,122.05 1232.68,122.05 1248.43,137.8 1248.43,200.87 1271.18,223.62 U1.18@1309.45,223.62
  Bottom Layer w7.87: v3(468.5,284.65) 468.5,770.04 525.14,826.67 735.73,826.67 736.79,827.74 ; v3(598.82,280.32) 604.2,280.32 742.12,142.4 1093.19,142.4 v3(1103.15,152.36)
  Bottom Layer w10: 736.79,827.74 762.99,853.94 v3(765.35,853.94)
GND: C1.2 C2.2 C3.2 C4.2 C7.2 C8.2 C9.2 C10.1 C11.1 C12.1 C13.1 C14.1 C15.1 C16.2 C17.1 C30.1 C31.1 C32.1 C33.1 C34.1 C35.1 C36.1 C37.1 C38.1 D3.2 JJ3.2 JJ4.2 P1.4 P2.4 P11.5 PWO.6 R14.1 R15.1 R49.2 R50.2 S1.9 S1.10 S1.11 S1.12 S1.13 S1.14 S1.15 S1.16 U1.0 U1.5 U1.9 U1.29 U1.38 U2.20 U3.1 U4.5 U5.3 U6.3 | length 919.3
  Top Layer w7.87: v6(427.56,751.58) 427.95,751.18 431.1,751.18 C38.1@452.76,751.18 ; v6(446.06,589.76) 444.09,589.76 450.79,596.46 C30.1@471.26,596.46 ; C34.1@452.76,1025.87 468.22,1025.87 470.87,1023.23 v6(474.41,1023.23) ; C33.1@452.76,1094.54 474.75,1094.54 475.2,1094.09 v6(473.23,1094.09) ; C32.1@452.76,1163.22 469.07,1163.22 v6(472.05,1160.24) ; v6(472.44,1218.5) 472.44,1223.62 464.17,1231.89 C31.1@452.76,1231.89 472.44,1212.21 v6@479.53,1212.21 ; 751.18,477.95 785.83,477.95 U3.1@790.55,482.68
  Top Layer w10: C7.2@1048.82,520.87 1049.21,520.47 C7.2@1049.61,520.47 ; v3(1089.76,464.57) C8.2@1106.69,464.57
  Top Layer w11.81: v3(794.88,1232.68) 795.28,1232.28 805.12,1232.28 825.98,1211.42 C12.1@825.98,1200.39 ; v3(824.02,1061.02) 822.44,1059.45 C14.1@822.44,1009.84 911.02,1009.84 923.62,997.24 U2.20@923.62,964.57 ; v3(1009.84,521.26) 1010.24,520.87 C7.2@1048.82,520.87 ; v3(1012.6,976.77) 1029.23,993.41 D3.2@1029.23,1011.5 ; U1.9@1309.45,400.79 1419.69,400.79 U1.0@1439.37,381.1 ; U1.5@1309.45,479.53 1392.13,479.53 1395.28,482.68 ; 1425.98,111.02 1429.13,114.17 C9.2@1481.5,114.17 ; 1502.76,379.53 1504.33,381.1 U1.29@1569.29,381.1
  other v1: 1629.53,41.73 1662.3,41.73 1695.08,41.73 1727.85,41.73 1760.63,41.73 2139.76,56.69 2172.54,56.69 2205.32,56.69 2238.09,56.69 2270.87,56.69 2420.08,61.81 2452.85,61.81 2485.63,61.81 2518.41,61.81 2551.18,61.81 1879.53,70.08 1912.3,70.08 1945.08,70.08 1977.85,70.08 2010.63,70.08 1647.24,74.8 1680.02,74.8 1712.8,74.8 1745.57,74.8 1778.35,74.8 2686.22,82.68 2719,82.68 2751.77,82.68 2784.55,82.68 2817.32,82.68 1320.87,83.47 1353.64,83.47 1386.42,83.47 1419.19,83.47 1451.97,83.47 2157.48,89.76 2190.26,89.76 2223.03,89.76 2255.81,89.76 2288.58,89.76 2437.8,94.88 2470.57,94.88 2503.35,94.88 2536.12,94.88 2568.9,94.88 1897.24,103.15 1930.02,103.15 1962.8,103.15 1995.57,103.15 2028.35,103.15 2703.94,115.75 2736.71,115.75 2769.49,115.75 2802.26,115.75 2835.04,115.75 1324.02,147.64 1356.79,147.64 1389.57,147.64 1422.34,147.64 1455.12,147.64 2674.02,158.66 2706.79,158.66 2739.57,158.66 2772.34,158.66 2805.12,158.66 1377.17,209.84 1418.6,209.84 1460.04,209.84 1501.48,209.84 1378.45,265.35 1419.88,265.35 1461.32,265.35 1502.76,265.35 1375.98,316.54 1417.42,316.54 1458.86,316.54 1500.3,316.54 1375.98,368.11 1417.42,368.11 1458.86,368.11 1500.3,368.11 1375.98,412.21 1417.42,412.21 1458.86,412.21 1500.3,412.21 575.1,431.99 1377.17,458.66 1418.6,458.66 1460.04,458.66 1501.48,458.66 1377.56,504.33 1419,504.33 1460.43,504.33 1501.87,504.33 574.1,508.99 1377.26,550.39 1418.7,550.39 1460.14,550.39 1501.58,550.39 844.1,562.99 1378.74,611.42 1411.52,611.42 1444.29,611.42 1477.07,611.42 1509.84,611.42 622.1,621.99 669.1,623.99 1569.69,642.13 1602.46,642.13 1635.24,642.13 1668.01,642.13 1700.79,642.13 864,648 1497.24,672.84 1587.4,675.2 1620.18,675.2 1652.95,675.2 1685.73,675.2 1718.5,675.2 1464.17,690.55 1497.24,705.61 1570.87,707.87 1603.64,707.87 1636.42,707.87 1669.19,707.87 1701.97,707.87 1464.17,723.33 1050.1,725.98 1082.87,725.98 1115.65,725.98 1148.43,725.98 1218.9,737.8 1251.67,737.8 1284.45,737.8 1317.23,737.8 1350,737.8 1497.24,738.39 1464.17,756.1 1067.82,759.06 1100.59,759.06 1133.37,759.06 1166.14,759.06 1497.24,771.16 1464.17,788.88 1537.01,801.58 1569.78,801.58 1602.56,801.58 1635.34,801.58 1668.11,801.58 1497.24,803.94 1464.17,821.65 1554.73,834.65 1587.5,834.65 1620.28,834.65 1653.05,834.65 1685.83,834.65 1538.19,867.32 1570.97,867.32 1603.74,867.32 1636.52,867.32 1669.29,867.32 908.66,990.95 551.58,1015.75 906.69,1036.22 572.05,1062.6 669.29,1080.71 906.69,1080.32 748.03,1089.37 829.92,1098.03 908.27,1124.8 674.02,1127.17 574.41,1128.74 730.71,1131.1 833.47,1131.1 3134.65,1574.8 3167.42,1574.8 3200.2,1574.8 3232.97,1574.8 3265.75,1574.8 3152.36,1607.87 3185.14,1607.87 3217.91,1607.87 3250.69,1607.87 3283.47,1607.87 3135.83,1640.55 3168.6,1640.55 3201.38,1640.55 3234.15,1640.55 3266.93,1640.55 1682.68,1679.53 1616.93,1680.71 1649.61,1697.24 1682.68,1712.3 1616.93,1713.49 1649.61,1730.02 1682.68,1745.08 1616.93,1746.26 1649.61,1762.8 1682.68,1777.85 1616.93,1779.04 1649.61,1795.57 1682.68,1810.63 1616.93,1811.81 1649.61,1828.35 2096.06,1852.36 2128.84,1852.36 2161.61,1852.36 2194.39,1852.36 2227.17,1852.36 2437.8,1852.36 2470.57,1852.36 2503.35,1852.36 2536.12,1852.36 2568.9,1852.36 2784.25,1852.36 2817.03,1852.36 2849.8,1852.36 2882.58,1852.36 2915.35,1852.36 1931.5,1901.58 1964.27,1901.58 1997.05,1901.58 2029.82,1901.58 2062.6,1901.58 2273.23,1901.58 2306,1901.58 2338.78,1901.58 2371.56,1901.58 2404.33,1901.58 2619.69,1901.58 2652.46,1901.58 2685.24,1901.58 2718.01,1901.58 2750.79,1901.58
  other v2: 264.57,81.5 637.33,186.66 2543.31,210.63 2584.25,248.03 354.33,258.66 72.44,333.47 1261.02,333.47 1170.47,381.5 2753.15,415.35 2577.56,444.09 2415.75,464.57 2054.33,490.16 2187.01,491.73 1968.9,498.82 1898.03,657.87 127.95,701.97 271.65,701.97 273.23,814.57 147.24,817.72 142.13,904.72 270.47,906.3 283.07,1007.87 149.61,1017.32 1140.55,1046.85 1430.32,1070.08 157.09,1109.45 285.83,1111.81 1478.35,1115.35 801.18,1119.69 1166.93,1121.26 1537.4,1127.56 3165.75,1144.49 1603.94,1161.81 157.09,1201.97 295.67,1209.06 3139.37,1244.88 182.28,1309.06 781.5,1348.43 1454.72,1413.78 164.57,1416.54 1359.84,1431.1 1419.69,1493.7 1524.41,1518.5 169.69,1521.26 237.01,1653.54 102.36,1658.66 1142.91,1888.19 1344.88,1888.19 1472.44,1888.19 301.97,1895.67 631.5,1895.67 818.5,1895.67 985.83,1895.67 509.06,1900.39
  other v6: 764.17,475.2
NetD1_2: D1.2 R3.2 | length 99.1
  Top Layer w10: D1.2@1040.07,47.74 1137.11,47.74 R3.2@1138.58,49.21
NetD2_2: D2.2 R2.2 | length 98.5
  Top Layer w10: D2.2@1040.07,119 R2.2@1138.58,119.06 R2.2@1138.58,119.06
NetD3_1: D3.1 R5.1 | length 57.2
  Top Layer w7.87: R5.1@972.44,1073.62 1028.36,1073.62 D3.1@1029.23,1074.5
NetJJ1_2: JJ1.2 Q3.1 Q3.2 Q3.3 Q7.1 Q7.2 Q7.3 R14.2 | length 47
  Top Layer w11.81: JJ1.2@2266.3,1355.91 2308.27,1355.91 2311.81,1359.45
NetJJ2_2: JJ2.2 Q4.1 Q4.2 Q4.3 Q8.1 Q8.2 Q8.3 R15.2 | length 52
  Top Layer w11.81: 2770.47,1355.51 2770.87,1355.91 JJ2.2@2822.28,1355.91
NetR12_1: R12.1 U4.2 | length 331.3
  Top Layer w15.75: R12.1@541.73,1603.94 607.09,1538.58 772.44,1538.58 U4.2@824.41,1590.55
NetR17_1: R17.1 U5.1 | length 718.5
  Top Layer w15.75: R17.1@543.31,1495.28 562.6,1475.98 1082.28,1475.98 U5.1@1203.54,1597.24
NetR19_1: R19.1 U6.1 | length 1000
  Top Layer w15.75: R19.1@539.37,1377.17 561.02,1398.82 1231.89,1398.82 1428.74,1595.67 U6.1@1448.82,1595.67
NRST: C30.2 P1.3 R30.2 U2.16 | length 948.3
  Top Layer w7.87: P1.3@166.54,629.13 208.07,629.13 249.41,587.8 413.42,587.8 450.62,625 524.61,625 ; C30.2@526.38,596.46 526.38,623.23 524.61,625 ; U2.16@903.35,861.22 835.63,861.22 773.62,799.21 773.62,746.6 690.8,663.78 R30.2@527.56,663.78 527.56,627.95 524.61,625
